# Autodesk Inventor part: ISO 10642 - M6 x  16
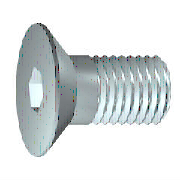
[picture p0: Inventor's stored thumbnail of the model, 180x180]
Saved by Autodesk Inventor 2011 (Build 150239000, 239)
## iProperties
IsCustomPart: 0
Created: 2010-02
Part Number: ISO 10642 - M6 x  16
Material: Steel
Description: Hexagon Socket Countersunk Head Screw-1 - Product grade A
Document SubType Name: Modeling
Standard: ISO 10642
Designer: 125296
Standard Revision: Second edition 2004-03-01
Standards Organization: ISO
Language: en-US
Size Designation: M6 x  16
Categories: <MemberInstance><Categories><Category DisplayName="Fasteners" InternalName="e4da775c-781d-43d5-af7c-5136215cf5a6" Mnemonic="FSTN"><Category DisplayName="Bolts"
Density: 7.85 g/cm^3
Mass: 4.46136 g
Surface Area: 5.34504 cm^2
Volume: 0.568326 cm^3
Author: 125296
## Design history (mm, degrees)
body "Solid1"
workplane "Work Plane1"
revolve "Body" stored, may be unused: angle "d13" = 90 deg
sketch "Sketch2"
  geometry: L1 (0, -7.938)-(0, 7.938) reference; L2 (-7.938, 0)-(7.938, 0) reference; L3 (2.309, 0)-(1.155, -2); L4 (1.155, -2)-(-1.155, -2); L5 (-1.155, -2)-(-2.309, 0); L6 (-2.309, 0)-(-1.155, 2); L7 (-1.155, 2)-(1.155, 2); L8 (1.155, 2)-(2.309, 0); A1 r 2.309 centre (0, 0) between (0, 2.309) and (2.309, 0) reference; 2 further points
  constraints: 12 end point, 2 coincident, 2 point on circle, 2 point on line, 12 other
extrude "Slot" join sketch "Sketch2" taper "d14" = 0 deg; stored distance "d30" = 10
feature "Thread" dims "d15" = 9 (= GEL), "d16" = 0
chamfer "Chamfer1" distance "d17" = 0.61345 (= -0.5 x SPD + 0.5 x GD); stored, may be unused: second distance "d18" = 0.61345 (= GUL), angle "d39" = 45 deg
sketch "Sketch1"
  geometry: L1 (16, 0)-(16, 3); L2 (16, 3)-(7, 3); L3 (7, 3)-(6.387, 3); L4 (0, 5.67)-(0, 2.309); L5 (0, 2.309)-(2.67, 2.309); L6 (2.67, 2.309)-(4.003, 0); L7 (4.003, 0)-(16, 0); L8 (0, 5.67)-(1.05, 5.67); L9 (1.05, 5.67)-(3.72, 3); L10 (6.387, 3)-(3.72, 3); L11 (7, 3)-(3.72, 3); L12 (3.72, 3)-(3.72, 3); L13 (-3.2, 0)-(19.2, 0) reference; L14 (0, -1.134)-(0, 6.804) reference
  constraints: 24 end point, 4 collinear, 3 parallel
  dimensions: "d0" = 16 distance between parallel lines of L4 L1 (= NLG); "d1" = 9 distance from line of L2.end L1 (= GEL); "d2" = 2.67 distance from line of L5.end L4 (= INTI); "d3" = 6 diameter of L2 L7 (= GD); "d6" = 3.72 distance from line of L9.end L4 (= KOH); "d7" = 45 deg angle of L9 L7 (= 0.5 x SEWI); "d8" = 4.6188 diameter of L5 L7 (= 1.1547 x SW); "d9" = 60 deg angle of L6 L7; "d10" = 11.34 diameter of L8 L7 (= KOD); "d11" = 6 diameter of L10 L7 (= BDM); "d12" = 0.61345 distance of L3.end L2.end (= GAL)
other parameters: "NLG" = 16 [user parameter; used in 1 equation term], "INTI" = 2.67 [user parameter; used in 1 equation term], "GEL" = 9 [user parameter; used in 2 equation terms], "GAL" = 0.61345 (= 0.61345 x PTC) [user parameter; used in 1 equation term], "KOH" = 3.72 [user parameter; used in 1 equation term], "KOD" = 11.34 [user parameter; used in 1 equation term], "GUL" = 0.61345 (= 0.61345 x PTC) [user parameter; used in 1 equation term], "SPD" = 4.7731 (= NND - 1.2269 x PTC) [user parameter; used in 1 equation term], "BDM" = 6 (= NND) [user parameter; used in 1 equation term], "GD" = 6 (= NND) [user parameter; used in 2 equation terms], "SEWI" = 90 deg [user parameter; used in 1 equation term], "d20" = 0, "SW" = 4 [user parameter; used in 1 equation term], "d43" = 0, "d44" = 0, "TOA" = 30 deg [user parameter], "GD1" = 4.7731 (= THREADDIA - 1.2269 x PTC) [user parameter], "EPV" = 6.72 [user parameter], "THREADDIA" = 6 [user parameter; used in 1 equation term], "PTC" = 1 [user parameter; used in 5 equation terms], "NND" = 6 [user parameter; used in 3 equation terms], "E0" = 4.62 [user parameter], "THREADDESC" = 12.345 [user parameter]
